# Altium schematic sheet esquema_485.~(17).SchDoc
size A4
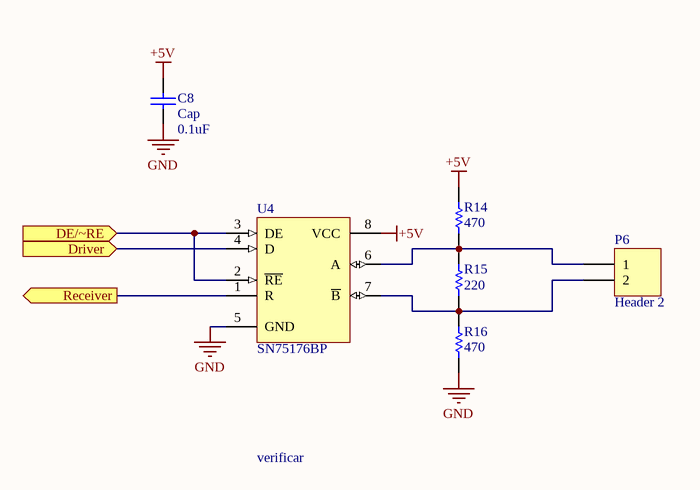
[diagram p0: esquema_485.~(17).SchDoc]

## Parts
C8  Cap  value 0.1uF  [CAPPR2.5-6.3X5]
P6  Header 2  [HDR1X2]
R14  value 470  [AXIAL-0.3]  (hidden comment: Carbon 1/8w 5%)
R15  value 220  [AXIAL-0.3]  (hidden comment: Carbon 1/8w 5%)
R16  value 470  [AXIAL-0.3]  (hidden comment: Carbon 1/8w 5%)
U4  SN75176BP  [P008]

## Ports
DE/~RE (in), Driver (in), Receiver (out)

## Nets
+5V: C8.2 R14.2 U4.8(VCC)
GND: C8.1 R16.1 U4.5(GND)
DE/~RE: U4.2(~{RE}) U4.3(DE) ; port DE/~RE
Driver: U4.4(D) ; port Driver
Receiver: U4.1(R) ; port Receiver
NetP6_1: P6.1 R14.1 R15.2 U4.6(A)
NetP6_2: P6.2 R15.1 R16.2 U4.7(~{B})

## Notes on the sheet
- verificar

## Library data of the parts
C8 = Cap: Capacitor
P6 = Header 2: Header, 2-Pin
R14-R16 = Res Semi: Semiconductor Resistor
U4 = SN75176BP: Differential Bus Transceiver; Note: Receiver Hysteresis of 50mV Typical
